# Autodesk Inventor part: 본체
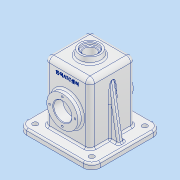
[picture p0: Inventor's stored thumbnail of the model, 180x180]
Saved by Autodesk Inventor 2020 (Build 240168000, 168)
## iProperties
Created: 2022-11
Part Number: 본체
Material: 알루미늄 6061
Document SubType Name: Modeling
Designer: user
Density: 2.7 g/cm^3
Appearance: 알루미늄 - 평지
Mass: 1133.07 g
Surface Area: 1017.37 cm^2
Volume: 419.654 cm^3
Author: user
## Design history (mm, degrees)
sketch "스케치1"
  geometry: L1 (62, 65)-(-62, 65); L2 (-62, 65)-(-62, -65); L3 (-62, -65)-(62, -65); L4 (62, -65)-(62, 65); L5 (62, 65)-(-62, -65); L6 (-62, 65)-(62, -65); 1 further point
  constraints: 12 end point, 2 midpoint, 2 parallel, 1 horizontal, 1 perpendicular
  dimensions: "d0" = 124 distance of L3.end L2.end; "d1" = 130 distance of L2.end L1.end
extrude "돌출1" new body sketch "스케치1" distance "d2" = 10; taper "d3" = 0 deg
sketch "스케치2"
  geometry: L1 (-40, -40)-(40, -40); L2 (40, -40)-(40, 40); L3 (40, 40)-(-40, 40); L4 (-40, 40)-(-40, -40); L5 (-40, -40)-(40, 40); L6 (40, -40)-(-40, 40); 1 further point
  constraints: 12 end point, 2 midpoint, 2 parallel, 1 horizontal, 1 perpendicular
  dimensions: "d4" = 80 distance of L3.end L2.end; "d5" = 80 distance of L2.end L1.end
extrude "돌출2" join sketch "스케치2" distance "d6" = 107; taper "d7" = 0 deg
fillet "모깎기1" dims "d8" = 8
sketch "스케치3"
  geometry: L1 (-33, -10)-(97, -10) reference; C1 r 27.5 at (32, 45); 2 further points
  constraints: 1 centre point, 1 midpoint, 1 vertical alignment
  dimensions: "d9" = 55 diameter of C1; "d10" = 55 distance from line of L1 C1.centre
extrude "돌출3" join sketch "스케치3" distance "d11" = 9; taper "d12" = 0 deg
sketch "스케치4"
  geometry: C1 r 27.5 at (32, 45) reference; C2 r 16 at (32, 45); 1 further point
  constraints: 1 centre point, 1 coincident
  dimensions: "d13" = 32 diameter of C2
extrude "돌출4" cut sketch "스케치4" extent not by distance; stored distance "d14" = 9; taper "d15" = 0 deg
fillet "모깎기2" dims "d16" = 15
fillet "모깎기3" dims "d17" = 3
sketch "스케치5"
  geometry: C1 r 16 at (0, 0) reference; C2 r 27.5 at (0, 0) reference; A1 r 22.5 centre (0, 0) between (0, 22.5) and (-22.5, 0); 3 further points
  constraints: 4 point on circle, 2 horizontal alignment, 2 vertical alignment, 1 centre point, 1 coincident
  dimensions: "d18" = 45 diameter of A1
hole "구멍1" sketch "스케치5" at (0, 22.5), (-22.5, 0), (0, -22.5), (22.5, 0) diameter "d19" = 3.242; stored, may be unused: countersink angle "d23" = 90 deg, drill point angle "d25" = 118 deg; dims "d20" = 8, "d21" = 4, "d22" = 2, "d24" = 10
sketch "스케치6"
  geometry: L1 (-32, -32)-(32, -32); L2 (32, -32)-(32, 32); L3 (32, 32)-(-32, 32); L4 (-32, 32)-(-32, -32); L5 (-32, -32)-(32, 32); L6 (32, -32)-(-32, 32); 2 further points
  constraints: 12 end point, 2 midpoint, 2 parallel, 1 coincident, 1 horizontal, 1 perpendicular
  dimensions: "d26" = 64 distance of L3.end L2.end; "d27" = 64 distance of L2.end L1.end
extrude "돌출5" cut sketch "스케치6" distance "d28" = 109; taper "d29" = 0 deg
fillet "모깎기4" dims "d30" = 3
chamfer "모따기1" distance "d31" = 1; stored, may be unused: second distance "d32" = 2, angle "d33" = 45 deg
sketch "스케치8"
  geometry: C1 r 20 at (0, 0); 1 further point
  constraints: 1 centre point, 1 coincident
  dimensions: "d34" = 40 diameter of C1
extrude "돌출6" join sketch "스케치8" distance "d35" = 10; taper "d36" = -10 deg
sketch "스케치9"
  geometry: C1 r 18.237 at (0, 0) reference; C2 r 14 at (0, 0)
  constraints: 1 centre point, 1 coincident
  dimensions: "d37" = 28 diameter of C2
extrude "돌출7" cut sketch "스케치9" distance "d38" = 4; taper "d39" = 0 deg
sketch "스케치10"
  geometry: C1 r 14 at (0, 0) reference; C2 r 10.5 at (0, 0)
  constraints: 1 centre point, 1 coincident
  dimensions: "d40" = 21 diameter of C2
extrude "돌출8" cut sketch "스케치10" distance "d41" = 14; taper "d42" = 0 deg
chamfer "모따기2" distance "d43" = 1; stored, may be unused: second distance "d44" = 2, angle "d45" = 45 deg
fillet "모깎기5" dims "d46" = 3
fillet "모깎기6" dims "d47" = 3
fillet "모깎기7" dims "d48" = 3
fillet "모깎기8" dims "d49" = 3
sketch "스케치11"
  geometry: C1 r 4.5 at (47, -50); C2 r 4.5 at (-47, -50); C3 r 4.5 at (-47, 50); C4 r 4.5 at (47, 50); A1 r 12 centre (47, -50) between (47, -62) and (59, -50) reference; A2 r 12 centre (47, 50) between (59, 50) and (47, 62) reference; A3 r 12 centre (-47, 50) between (-47, 62) and (-59, 50) reference; A4 r 12 centre (-47, -50) between (-59, -50) and (-47, -62) reference; 1 further point
  constraints: 4 centre point, 4 coincident
  dimensions: "d50" = 9 diameter of C1; "d51" = 9 diameter of C2; "d52" = 9 diameter of C3; "d53" = 9 diameter of C4
extrude "돌출9" cut sketch "스케치11" distance "d54" = 14; taper "d55" = 0 deg
fillet "모깎기9" dims "d56" = 3
sketch "스케치12"
  geometry: L1 (10, -40)-(10, -55.693); L2 (10, -55.693)-(99, -40); L3 (99, -40)-(10, -40); L4 (0, -65)-(7, -65) reference; L5 (10, -45.5)-(10, -54.5) reference; L6 (13, -40)-(109, -40) reference; L7 (10, -50)-(10, -62) reference; L8 (127, -15)-(127, 15) reference; 3 further points
  constraints: 6 end point, 2 midpoint, 2 point on line, 1 perpendicular, 1 vertical
  dimensions: "d59" = 100 deg angle of L2 L7; "d60" = 28 distance from line of L8 L2.end
extrude "돌출10" join sketch "스케치12" stored distance "d61" = 10; taper "d62" = 0 deg
fillet "모깎기10" dims "d63" = 3
fillet "모깎기11" dims "d64" = 3
node "작업 평면1"
sketch "스케치13"
  geometry: L1 (72, -96)-(72, 0) reference; L2 (13.763, 18)-(50.237, 18) reference; 2 further points
  constraints: 1 other
  dimensions: "d66" = 40 distance from line of L1 point (32, -7); "d67" = 25 distance from line of L2 point (32, -7)
feature "엠보싱1" sketch "스케치13" dims "d0" = 124, "d1" = 130, "d68" = 0.5, "d69" = 0
node "솔리드1"
mirror "미러1"
mirror "미러2"
mirror "미러3"
feature "A9D066F2-1C7D-4E18-AEED-F7BC21143FA4" dims "d19" = 3.242, "d20" = 8, "d21" = 4, "d22" = 2, "d23" = 90 deg, "d24" = 10, "d25" = 118 deg
